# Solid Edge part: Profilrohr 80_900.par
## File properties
Username: ahadarics
Dokumentum tartalom típus: 0
Author: ahadarics
Last saved by: ahadarics
Revision: 99
Sűrűség: 0,000 kg/m^3
Pontosság: 0,990
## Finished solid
Body 1: solid body, 147 faces, 435 edges, 290 vertices.
  Faces by surface: cylinder 85, plane 62
  Edges by curve: line 265, circle 170
Bounding box of the edges (mm): 86.600 x 86.600 x 948.000, from (-43.3, -43.3, -911.5) to (43.3, 43.3, 36.5).
Cylindrical faces by radius (mm): R0.1 x8, R0.2 x30, R0.5 x22, R1 x8, R4.6 x4, R7 x4, R40 x1, R42.7 x8
Planar faces by outward normal: +x 6, +y 6, +z 1, -x 4, -y 4, -z 1, oblique 40
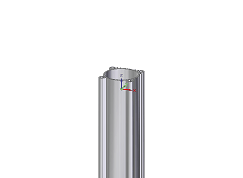
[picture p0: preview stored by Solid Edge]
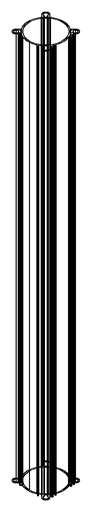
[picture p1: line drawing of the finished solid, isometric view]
